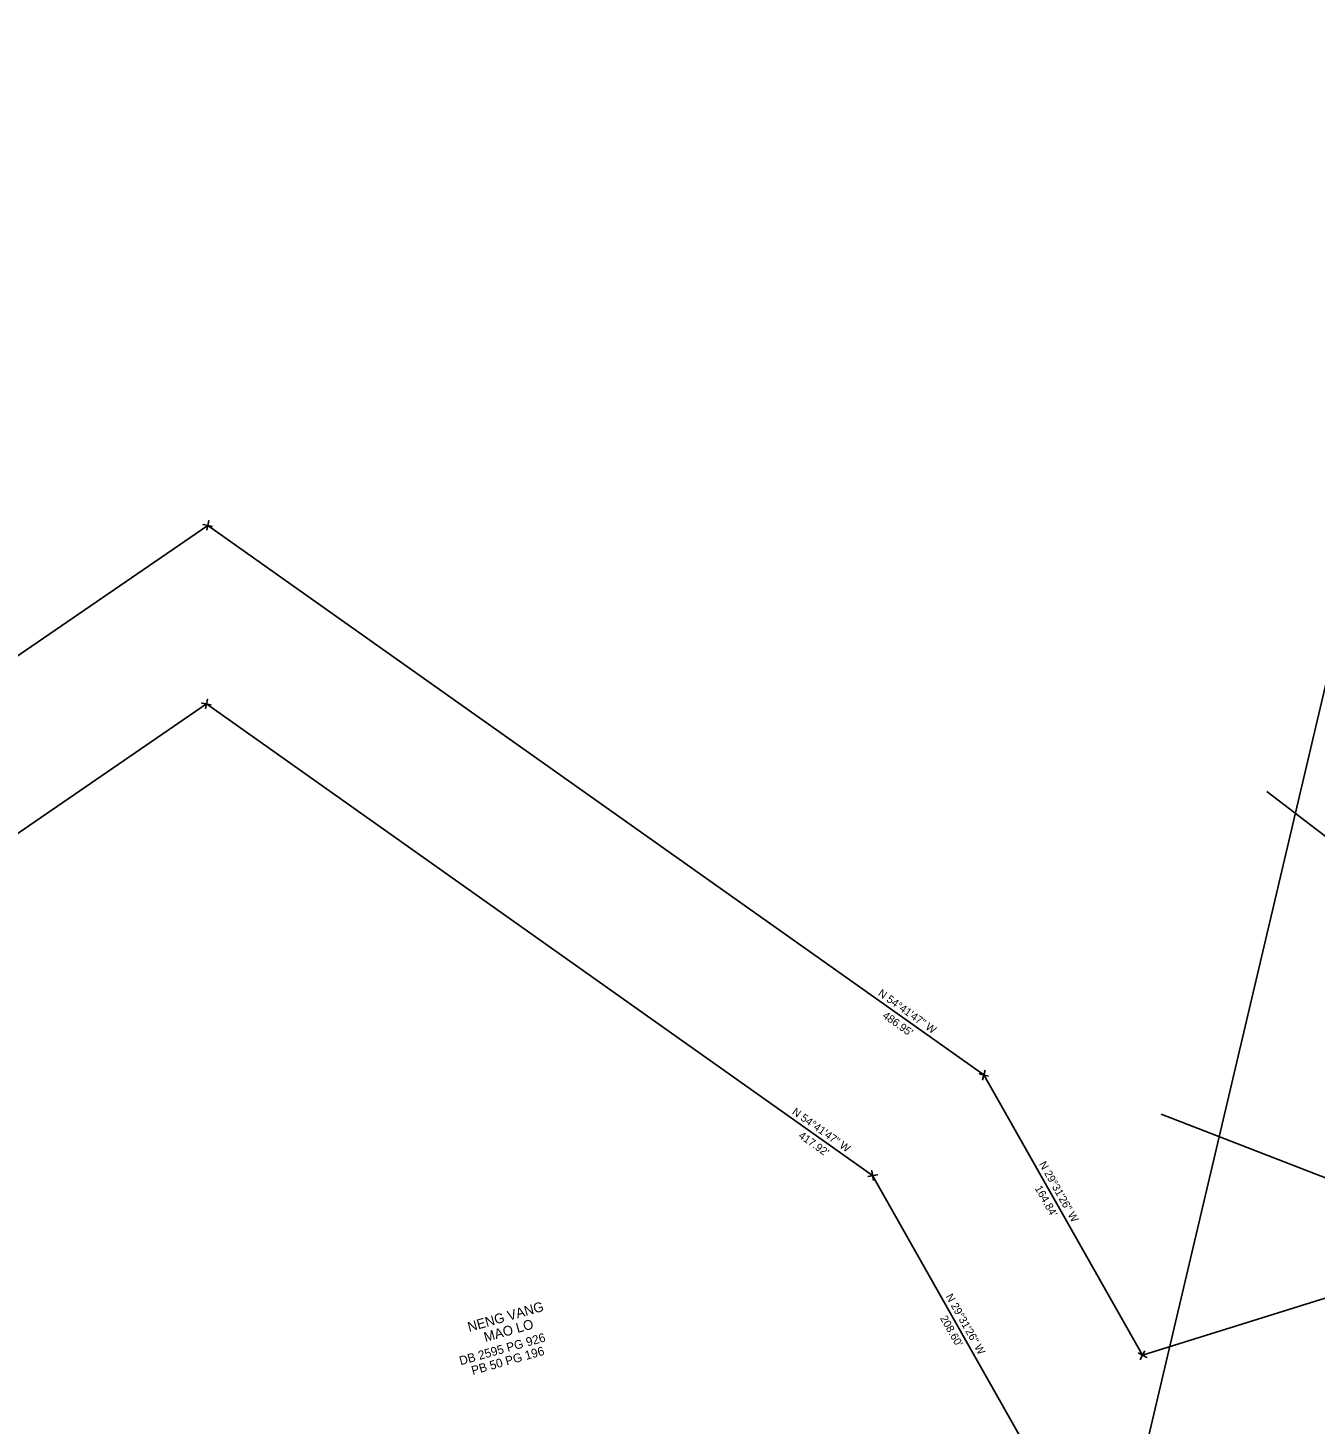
# Model space of a CAD drawing. Extents: x 1316460 to 1321645, y 684173 to 687077.
# Drawn here: x 1318467 to 1319126, y 685726 to 686441 of the extents above; entities that cross this region are included whole.
import ezdxf

# ---------------------------------------------------------------- set-up
doc = ezdxf.new("R2010")
doc.units = 0
for name, color, linetype in [('Exist Hydrographic Water Edge Cogo Elevation', 7, 'Continuous'), ('Exist Property Corner CELL', 7, 'Continuous'), ('Exist Property Deed Book Text', 7, 'Continuous'), ('Exist Property Line', 7, 'Continuous'), ('Exist Property Line Text', 7, 'Continuous'), ('Exist Property Owner Text', 7, 'Continuous'), ('Exist Vegetation Woods Line', 7, 'Continuous'), ('Old_Level_59', 7, 'Continuous')]:
    doc.layers.add(name, color=color, linetype=linetype)

msp = doc.modelspace()

# ---------------------------------------------------------------- linework, layer by layer
at = {"layer": 'Exist Hydrographic Water Edge Cogo Elevation'}
msp.add_lwpolyline([(1319047.45, 685884.84), (1319132.52, 685852.03), (1319257.48, 685744.84)], dxfattribs=at)
at = {"layer": 'Exist Property Corner CELL'}
for p, q in [((1318559.33, 686186.39), (1318559.33, 686186.39)), ((1318558.65, 686094.97), (1318558.65, 686094.97)), ((1318956.73, 685904.98), (1318956.73, 685904.98)), ((1318899.71, 685853.45), (1318899.71, 685853.45)), ((1319037.96, 685761.54), (1319037.96, 685761.54))]:
    msp.add_line(p, q, dxfattribs=at)
for points in [[(1318558.87, 686183.93), (1318559.78, 686188.85), (1318559.33, 686186.39), (1318556.87, 686186.85), (1318561.78, 686185.93)], [(1318558.19, 686092.51), (1318559.11, 686097.43), (1318558.65, 686094.97), (1318556.19, 686095.43), (1318561.11, 686094.51)], [(1318959.14, 685904.31), (1318954.32, 685905.65), (1318956.73, 685904.98), (1318956.06, 685902.57), (1318957.39, 685907.39)], [(1318897.25, 685853.03), (1318902.18, 685853.87), (1318899.71, 685853.45), (1318899.29, 685855.92), (1318900.14, 685850.99)], [(1319039.12, 685763.76), (1319036.8, 685759.33), (1319037.96, 685761.54), (1319040.17, 685760.38), (1319035.74, 685762.7)]]:
    msp.add_lwpolyline(points, dxfattribs=at)
at = {"layer": 'Exist Property Line'}
for p, q in [((1318559.33, 686186.39), (1318011.63, 685810.62)), ((1318956.73, 685904.98), (1318559.33, 686186.39)), ((1318558.65, 686094.97), (1318038.51, 685738.1)), ((1318899.71, 685853.45), (1318558.65, 686094.97)), ((1319037.96, 685761.54), (1318956.73, 685904.98)), ((1319414.78, 685878.99), (1319037.96, 685761.54)), ((1319002.51, 685671.94), (1318899.71, 685853.45))]:
    msp.add_line(p, q, dxfattribs=at)
at = {"layer": 'Exist Vegetation Woods Line'}
msp.add_lwpolyline([(1319101.66, 686050.12), (1319196.68, 685977.46)], dxfattribs=at)
at = {"layer": 'Old_Level_59'}
msp.add_lwpolyline([(1318697.3, 685264.68), (1318675.61, 685496.37), (1319013.72, 685603.72), (1319178.5, 686302.95), (1319290.7, 686462.26), (1319434.76, 686395.34), (1319426.96, 685366.75), (1319230.41, 685144.48), (1318730.33, 685054.78)], close=True, dxfattribs=at)

# ---------------------------------------------------------------- texts
at = {"layer": 'Exist Property Deed Book Text'}
for s, p in [('DB 2595 PG 926', (1318688.82, 685756.33)), ('PB 50 PG 196', (1318695.02, 685751.32))]:
    msp.add_text(s, height=4.5, rotation=15.73495, dxfattribs=at).set_placement(p)
at = {"layer": 'Exist Property Line Text'}
for s, rotation, p in [('N 54%%D41\'47" W', 324.69639, (1318902.18, 685946)), ("486.95'", 324.69639, (1318904.47, 685934.58)), ('N 54%%D41\'47" W', 324.69639, (1318858.17, 685885.27)), ("417.92'", 324.69639, (1318861.46, 685873.13)), ('N 29%%D31\'26" W', 299.52389, (1318984.84, 685859.4)), ("164.84'", 299.52389, (1318982.65, 685847.02)), ('N 29%%D31\'26" W', 299.52389, (1318937.04, 685791.59)), ("208.60'", 299.52389, (1318934.15, 685780.47))]:
    msp.add_text(s, height=4, rotation=rotation, dxfattribs=at).set_placement(p)
at = {"layer": 'Exist Property Owner Text'}
for s, p in [('NENG VANG', (1318693.16, 685773.4)), ('MAO LO', (1318701.49, 685768.22))]:
    msp.add_text(s, height=5, rotation=15.73495, dxfattribs=at).set_placement(p)

doc.saveas('drawing.dxf')
